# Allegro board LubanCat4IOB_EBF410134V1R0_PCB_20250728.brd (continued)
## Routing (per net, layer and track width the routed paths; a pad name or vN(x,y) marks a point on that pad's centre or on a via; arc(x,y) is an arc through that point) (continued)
VBUS_TYPEC: length 50.2
  TOP w0.203: J30.A9 26.63,96.58 26.87,96.82 J30.B4
  TOP w0.254: v1(29.46,98.55) 29.46,98.04 29.37,97.94 J30.B9 29.37,96.85 29.13,96.61 J30.A4 29.13,95.37 29.04,95.28 29.04,94.9 28.83,94.68 v1(28.83,94.11) ; J30.B4 26.87,98.48 v1(26.8,98.55) ; v1(21.01,82.26) 20.7,82.57 20.7,92.2 20.32,92.58 20.32,93.83 v1(19.68,94.46)
  BOTTOM w0.152: U39.2 26.03,69.47 C206.1
  BOTTOM w0.254: v1(19.68,94.46) 27.79,94.46
  BOTTOM w0.305: v1(21.01,82.26) 20.83,82.08 20.83,81.54 20.14,80.85 20.14,75.56 20.45,75.25 25.58,75.25 27.49,73.34 27.49,69.95 27,69.46 C206.1
  vias: v1(26.8,99.54)
VCC3V3_SYS: length 12.1
  BOTTOM w0.305: C17.1 8.81,46.36 9.45,47.01 9.45,52.2 8.69,52.97 C10.1 R6.1
  vias: v1(6.99,45.08) v1(6.99,44.07) v1(8,45.08) v1(8,44.07) v1(19.3,42.67) v1(19.3,41.53) v1(123.06,63.75) v1(124.08,63.75) v1(126.87,95.12) v1(126.87,94.11)
VCC5V0_SYS: length 56.8
  TOP w0.152: J3.1 J3.2 ; J3.4 v1(24.11,27.08) J3.3 ; J3.5 J3.6
  TOP w0.254: U4.5 v1(2.08,70.61)
  TOP w0.305: v1(18.54,19.81) 17.4,19.81 16.26,18.67 16.26,14.35 15.38,13.47 R36.1 R35.1 R34.1
  BOTTOM w0.152: v1(24.11,27.08) 24.49,26.7 24.49,22.94 24.94,22.48 R238.1 ; 128.52,89.93 v1(128.52,89.86) 128.52,89.66 128.61,89.58 C136.1 ; C31.1 v1(19.43,27.68) ; U39.12 22.99,71.89 C205.1
  BOTTOM w0.381: v1(21.46,73.4) C204.1 22.44,72.44 C205.1 ; R18.1 8,65.28 7.75,65.02 7.75,62.77 6.99,62.01 5,62.01 ; C29.1 3.93,62.48 3.55,62.86 2.46,62.86 2.08,63.24 v1(2.08,70.61)
  BOTTOM w0.508: R11.1 9.53,58.7 8.51,57.69 v1(6.44,57.69)
  vias: v1(4.45,59.69) v1(4.45,58.69) v1(4.45,57.69) v1(5.44,59.69) v1(5.44,58.69) v1(5.44,57.69) v1(6.44,59.69) v1(6.44,58.69) v1(19.43,30.68) v1(19.43,29.68) v1(19.43,28.68) v1(19.68,92.84) v1(20.43,30.68) v1(20.43,29.68) v1(20.43,28.68) v1(20.43,27.68) v1(20.57,48.89) v1(20.94,92.84) v1(21.46,48.89) v1(22.48,82.29) v1(23.37,82.29) v1(89.03,101.09) v1(90.04,101.09) v1(102.36,101.09) v1(103.38,101.09) v1(123.06,58.67) v1(124.08,58.67) v1(126.62,64.64) v1(126.62,63.63) v1(126.62,42.54) v1(126.62,41.53) v1(127.64,64.64) v1(127.64,63.63) v1(127.64,42.54) v1(127.64,41.53) v1(128.52,90.66)
VCC_1V8_S0: length 59.4
  TOP w0.203: 28.5,29.72 27.71,28.93 J3.21 J3.22
  TOP w0.508: v1(56.01,68.2) v1(56.01,67.05) 55.02,66.06 52.2,66.06 45.72,59.59 45.72,53.97 31.88,40.13 31.88,30.22 31.37,29.72 28.5,29.72
  BOTTOM w0.381: R185.1 v1(56.01,67.05) ; R188.1 v1(56.01,68.2)
VCC_1V8_S3: length 206.1
  TOP w0.203: J3.19 J3.20 27.31,23.49 v1(27.3,23.48)
  TOP w0.305: v1(25.79,23.5) 24.71,22.43 v1(17.4,22.43) 9.58,22.43 8.76,23.24 8.76,29.38 8.15,29.99 3.68,29.99 v1(3.56,29.86)
  TOP w0.381: v1(17.91,8.91) 99.97,8.91 101.73,10.67 101.73,26.93 102.11,27.31 R61.1
  ART03 w0.381: v1(3.56,29.86) 2.73,30.69 2.73,40.45 1.4,41.78 1.4,79.5 v1(1.78,79.88)
  BOTTOM w0.254: v1(1.78,79.88) 2.67,80.77 2.67,81.41 2.93,81.67 R46.1 R47.1
  BOTTOM w0.381: v1(17.4,22.43) 17.91,21.92 v1(17.91,8.91)
  BOTTOM w0.508: v1(25.79,23.5) C35.1 27.28,23.5 v1(27.3,23.48)
VCC_3V3_S3: length 251.8
  TOP w0.203: J3.14 J3.13 26.11,29.26 25.57,29.8 v1(25.57,31.74)
  TOP w0.305: v1(27.3,19.81) v1(21.73,19.81)
  TOP w0.381: v1(19.68,45.97) 18.31,45.97 17.55,46.73 17.55,65.78 16.88,66.46 16.88,76.49 16.11,77.26 v1(9.78,77.26)
  TOP w0.508: R56.1 109.98,29.46 109.7,29.74 104.5,29.74 104.04,30.2 104.04,31.64 103.65,32.03 101.35,32.03 100.61,31.29 100.61,11.07 99.82,10.29 v1(18.54,10.29)
  ART03 w0.381: v1(44.83,78.21) 31.24,78.21 30.48,77.45 30.48,70.76 29.59,69.87 26.59,69.87 24.97,68.25 24.97,65.19 v1(24.26,64.48) v1(23.05,64.48) 23.04,64.46 v1(21.57,64.46)
  BOTTOM w0.152: v1(25.57,31.74) 25.54,31.77 C36.1
  BOTTOM w0.254: 27.31,19.8 v1(27.3,19.81) ; 24.89,65.79 24.89,66.8 23.99,67.7 U39.4 24.45,68.72 U39.3 ; 24.89,65.79 C211.1 ; 24.89,65.79 R232.1 v1(24.26,64.48) ; v1(23.05,64.48) 23.11,64.54 R230.1 ; U5.5 20.34,17.67 20.18,17.52 R25.1 ; v1(21.57,64.46) 21.59,64.46 21.97,64.85 R231.1 ; U6.5 25.18,17.67 R29.1
  BOTTOM w0.305: v1(21.73,19.81) C40.1 21.73,18.55 21.33,18.15 U5.5 ; 27.31,19.8 C42.1 27.31,18.55 26.91,18.15 U6.5
  BOTTOM w0.381: v1(9.78,77.26) 9.78,83.37 10.54,84.14 D5.2 ; v1(44.83,78.21) 45.33,78.71 R233.1
  BOTTOM w0.508: v1(19.68,45.97) 19.68,56.26 21.72,58.29 23.11,58.29 24.13,59.31 24.13,62.99 25.53,64.39 C211.1
  vias: v1(20.57,45.97) v1(21.46,34.03) v1(21.46,33.15) v1(24.77,31.74)
VCC_3V3_SD: length 5.3
  TOP w0.508: R56.2 109.97,27.3 C58.1 C59.1 110,24.74 J10.4
VCC_12V: length 10.8
  TOP w0.254: U4.1 5.2,72.97
  BOTTOM w0.254: v1(6.86,55.24) 6.1,56 R8.1
  BOTTOM w0.279: R15.1 v1(6.99,74.93)
  BOTTOM w0.508: v1(8.86,55.24) 10.79,55.24 11.3,55.75 R10.1
  vias: v1(6.99,76.96) v1(6.99,75.94) v1(7.87,76.96) v1(7.87,75.94) v1(7.87,74.93) v1(12.83,82.29) v1(12.83,81.28) v1(13.84,82.29) v1(13.84,81.28) v1(79.25,86.64) v1(80.14,86.64)
VCCA1V8_CODEC: length 40
  TOP w0.381: v1(57.79,60.32) v1(55.12,60.32)
  BOTTOM w0.254: R200.1 48.39,74.8 48.78,75.19 R207.1 C187.1
  BOTTOM w0.381: C187.1 52.83,73.78 53.59,73.02 53.59,70.74 54.99,69.34 57.03,69.34 57.79,68.58 v1(57.79,60.32) C165.1 57.49,59.13 C164.1 57.67,57.99 R184.2 ; v1(55.12,60.32) 54.24,61.2 C174.1 C175.1 54.24,64 52.58,65.66 52.58,68.83 52.32,69.09
VCCA3V3_CODEC: length 45.2
  TOP w0.305: v1(41.53,66.93) 42.16,67.56 44.02,67.56 45.34,68.88 45.9,68.88 46.46,69.44 46.46,78.38 44.45,80.39 R205.1 47.19,82.94 47.5,83.24 47.5,84.94 47.8,85.24 54.56,85.24 54.86,84.94 R192.2
  TOP w0.508: v1(42.29,62.48) 41.53,63.24 v1(41.53,65.44) v1(41.53,66.93)
  BOTTOM w0.381: R186.1 42.03,68.7 41.53,68.2 v1(41.53,66.93) ; v1(41.53,65.44) 42.06,65.44 R187.1
  BOTTOM w0.508: R189.2 40.72,61.71 C172.1 41.32,61.71 C173.1 v1(42.29,62.48)
VCCA_1V8_S0: length 147.3
  TOP w0.203: v1(27.56,29.73) 26.91,29.08 J3.17 J3.18
  TOP w0.254: v1(8.26,32.89) v1(8.26,37.97)
  TOP w0.305: v1(18.14,32.38) 12.67,32.38 12.17,32.89 v1(8.26,32.89)
  TOP w0.381: v1(25.43,50.04) 25.43,35.5 26.19,34.74 v1(27.57,34.74)
  ART03 w0.381: v1(34.16,69.34) 34.03,69.21 26.77,69.21 25.53,67.97 v1(25.53,62.85)
  ART03 w0.762: v1(58.67,35.43) 56.97,33.73 30.18,33.73 28.19,31.74 v1(27.57,31.74)
  BOTTOM w0.203: v1(8.26,32.89) 7.63,32.27 R30.2 ; R32.2 7.89,37.61 v1(8.26,37.97)
  BOTTOM w0.305: v1(27.57,31.74) 28.22,32.39 28.22,34.09 v1(27.57,34.74) 27.33,34.97 18.75,34.97 18.14,34.37 v1(18.14,32.38)
  BOTTOM w0.381: v1(58.67,35.43) 58.67,36.7 59.86,37.89 59.86,41.61 57.38,44.09 57.38,52.42 58.67,53.71 C162.1 C163.1 R184.1 ; v1(34.16,69.34) 34.16,69.34 33.78,69.34 33.15,69.98 33.15,73.17 33.66,73.67 R23.1 ; v1(25.43,50.04) 25.43,58.39 24.89,58.93 24.89,62.21 v1(25.53,62.85)
  BOTTOM w0.508: v1(27.57,31.74) C34.1 27.57,29.73 v1(27.56,29.73)
VCCA_3V3_S0: length 53.5
  TOP w0.203: J3.16 J3.15 26.51,29.68 v1(26.56,29.73)
  TOP w0.508: v1(26.57,31.74) 26.57,32.64 26.06,33.15 24.17,33.15 23.15,34.16 23.15,52.96 23.79,53.59 v1(29.08,53.59)
  BOTTOM w0.508: v1(29.08,53.59) 29.08,59.57 30.23,60.71 C170.1 C171.1 R189.1 ; v1(26.56,29.73) 26.53,29.75 C33.1 26.53,31.71 v1(26.57,31.74)
VDD_3V3: length 235.5
  TOP w0.254: v1(103.25,19.43) 105.05,17.63 120.75,17.63 121.8,18.68 R164.1 ; R164.1 R162.1 v1(124.97,18) ; R164.1 v1(123.83,18)
  ART03 w0.381: v1(78.74,92.96) 76.96,91.18 v1(74.04,91.18) 73.53,90.68 67.82,90.68 v1(67.18,90.04)
  BOTTOM w0.152: R150.1 R154.1 121.98,71.57 121.98,76.02 120.9,77.1 120.9,80.74 121.16,80.99 v1(121.16,81.68)
  BOTTOM w0.254: v1(122.56,81.52) 123.06,81.02 123.06,80.01 122.56,79.51 R148.1 R152.1 ; R130.1 67.94,90.8 v1(67.18,90.04) 67.18,90.03 R129.1 R127.1 64.25,89.88 Q7.1 ; R162.1 v1(124.97,18) ; R132.1 64.89,100.2 66.79,100.2 R135.1 R133.1 70.24,100.2 71.88,100.2 72.26,99.82 72.26,97.92 72.64,97.53 76.71,97.53 78.36,95.88 78.36,93.34 v1(78.74,92.96) ; R164.1 v1(123.83,18)
  BOTTOM w0.381: 12.57,13.08 12.19,13.46 9.91,13.46 9.53,13.08 R44.1 ; 12.57,13.08 12.85,13.36 16.07,13.36 17.2,14.48 17.2,21.67 16.51,22.35 v1(16.51,44.07) ; 12.57,13.08 R43.1 ; U9.16 45.59,48.01 46.11,47.49 C54.1 47.63,47.49 48.23,46.89 v1(48.23,42.42) ; Q6.2 95.77,44.42 C94.1 R110.1 95.77,41.78 96.15,41.4 98.81,41.4 99.19,41.02 99.19,19.81 99.57,19.43 v1(103.25,19.43) ; v1(74.04,91.18) 75.31,91.18 75.69,90.8 75.69,85.22 v1(75.31,84.83) ; v1(121.16,81.68) v1(121.16,82.68)
  BOTTOM w0.508: R240.2 C90.1 117.72,77.8 117.14,78.38 115.98,78.38 115.49,78.87 115.49,81.14 117.03,82.68 v1(121.16,82.68)
  BOTTOM w0.762: 59.56,45.32 59.56,51.18 61.09,52.7 61.09,55.32 61.85,56.08 61.85,71.19 61.44,71.59 61.44,75.02 64.95,78.53 66.14,78.53 67.14,79.53 68.85,79.53 74.16,84.83 v1(74.31,84.83) v1(75.31,84.83)
  vias: v1(29.1,44.32) v1(29.97,44.32) v1(30.99,44.32) v1(60.43,43.69) v1(61.44,43.69) v1(61.47,42.67) v1(91.69,85.34)
VDD_5V: length 72.4
  BOTTOM w0.254: Q9.1 64.71,96.22 65.4,96.91 69.72,96.91 70.1,96.53 70.1,94.87 70.38,94.59 71.6,94.59 73.03,96.01 74.93,96.01 75.56,95.38 75.56,91.95 76.3,91.21 76.3,87.07 D28.2
  BOTTOM w0.508: v1(60.45,48.3) 60.45,50.8 61.98,52.32 61.98,54.84 62.71,55.57 62.71,71.57 62.31,71.97 62.31,74.49 63.4,75.58 65.63,75.58 66.19,76.14 66.19,77.26 67.56,78.63 69.08,78.63 74.14,83.69 76.27,83.69 77.14,84.56 D28.2
  vias: v1(29.12,49.15) v1(29.97,49.15) v1(61.47,48.3)
5V0_CAM0/1:
  vias: v1(128.27,55.88) v1(128.27,54.86) v1(129.29,55.88) v1(129.29,54.86)
5V0_CAM2/3:
  vias: v1(128.27,33.88) v1(128.27,32.86) v1(129.29,33.88) v1(129.29,32.86)
B_DM1: length 28.9
  TOP w0.135: J16.2 87.05,93.38 86.92,93.52 86.92,94.76 87.23,95.06 90.68,95.06 93.4,92.34 96.1,92.34 96.37,92.07 96.37,90.17 v1(96.11,89.91)
  BOTTOM w0.135: R116.1 89.71,82.97 89.71,83.49 89.49,83.7 89.49,84.02 89.4,84.12 U16.7 U16.4 89.4,86.06 89.49,86.16 89.49,86.74 90.26,87.5 95.5,87.5 96.33,88.33 96.33,89.69 v1(96.11,89.91)
B_DM2: length 10.3
  TOP w0.135: v1(86.96,86.82) 86.97,86.82 87.31,87.17 87.75,87.17 88,87.41 88,89.13 87.66,89.47 87.66,89.92 J16.11
  BOTTOM w0.135: v1(86.96,86.82) 87.14,87.01 87.15,87.01 87.28,87.14 87.84,87.14 88.09,86.89 88.09,86.25 87.9,86.06 U16.1 U16.10 87.9,84.21 88.09,84.02 88.09,83.38 R112.1
B_DM3: length 36.5
  BOTTOM w0.135: J17.2 102,89.89 101.87,89.75 99.35,89.75 96.27,86.67 96.27,79.01 98.81,76.47 98.81,69.1 99.28,68.62 99.28,64.4 98.58,63.7 98.06,63.7 97.87,63.89 U18.9 U18.2 96.02,63.89 95.83,63.7 95.17,63.7 R114.1
B_DP1: length 29.6
  TOP w0.135: v1(96.77,89.91) 96.68,90.01 96.68,92.2 96.23,92.65 93.53,92.65 90.81,95.38 87.1,95.38 86.61,94.89 86.61,93.52 86.47,93.38 J16.3
  BOTTOM w0.135: R117.1 90.04,83.05 90.04,83.59 89.81,83.83 89.81,84.02 89.9,84.12 U16.6 U16.5 89.9,86.06 89.81,86.16 89.81,86.61 90.39,87.19 95.63,87.19 96.65,88.2 96.65,89.79 v1(96.77,89.91)
B_DP2: length 10.4
  TOP w0.135: v1(86.96,87.48) 87.55,87.48 87.69,87.62 87.69,89 86.5,90.18 J16.12
  BOTTOM w0.135: R113.1 88.4,82.68 U16.9 U16.2 88.4,87.02 87.97,87.45 86.99,87.45 v1(86.96,87.48)
B_DP3: length 36.2
  BOTTOM w0.135: J17.3 102,89.31 101.87,89.44 99.48,89.44 96.58,86.54 96.58,79.14 99.12,76.6 99.12,69.23 99.59,68.75 99.59,64.27 98.71,63.39 U18.10 U18.1 95.96,63.39 95.96,63.38 95,63.38 R115.1
BAT_RTC: length 6.4
  BOTTOM w0.381: J8.1 16.07,84.59 D6.2 C50.1 12.44,84.59 11.39,85.64 D5.1
BD_CH3: length 5.2
  TOP w0.152: v1(32.77,76.96) 32.91,76.81 J4.48
  BOTTOM w0.152: R23.2 33.66,75.44 R24.1 C38.1 33.27,77.47 v1(32.77,76.96)
CAM0/1_PWR_EN: length 110.3
  TOP w0.152: J5.69 62.88,29.19 62.31,29.77 62.31,32.18 61.99,32.49 v1(60.1,32.49)
  ART03 w0.14: v1(126.11,59.56) 126.11,58.64 126.33,58.42 128.37,58.42 128.78,58.01 128.78,55.55 128.93,55.4 129.44,55.4 129.77,55.07 129.77,43.53 128.27,42.04 122.29,42.04 121.66,41.4 119.13,41.4 115.06,45.46 102.87,45.46 102.36,44.96 102.36,34.97 102.06,34.67 62.28,34.67 v1(60.1,32.49)
  BOTTOM w0.152: v1(126.11,59.56) 126.11,59.57 R165.1
CAM0_NRST: length 174.9
  TOP w0.152: v1(18.82,69.21) 18.31,69.72 18.31,72.59 18.62,72.9 23.44,72.9 24.51,73.96 J4.6
  ART03 w0.14: v1(119.63,42.67) 115.66,46.64 115.61,46.64 115.58,46.67 101.23,46.67 100.46,45.9 100.46,40.54 100.05,40.13 59.13,40.13 58.57,40.69 54.79,40.69 54.28,40.18 14.91,40.18 14.63,40.46 14.63,65.56 18.29,69.21 v1(18.82,69.21)
  BOTTOM w0.152: J21.22 125.72,54.75 124.76,55.7 122.25,55.7 118.51,51.96 118.51,43.79 v1(119.63,42.67)
CAM0_PWDN: length 178.6
  TOP w0.152: J4.4 24.11,74.34 23.81,74.04 18.52,74.04 17.83,73.35 17.83,70.22 v1(17.82,70.21)
  ART03 w0.14: v1(128.91,45.85) 128.91,43.68 128.28,43.06 124.34,43.06 123.83,42.54 121.93,42.54 121.16,41.78 119.25,41.78 115.19,45.85 102.23,45.85 101.73,45.34 101.73,39.17 101.42,38.86 58.88,38.86 58.5,38.48 55.93,38.48 55.55,38.86 14.22,38.86 13.74,39.34 13.74,66.27 17.69,70.21 v1(17.82,70.21)
  BOTTOM w0.152: v1(128.91,45.85) 129.54,46.48 129.54,51 129.29,51.25 J21.15
CAM1_NRST: length 162.4
  TOP w0.152: v1(124.97,44.96) 125.26,45.25 J22.22 ; v1(24,75.99) 25.48,75.99 25.71,75.76 J4.12
  ART03 w0.14: v1(24,75.99) 24,74.52 20.24,70.76 20.24,69.04 19.91,68.71 18.49,68.71 15.14,65.35 15.14,41.02 15.39,40.77 53.92,40.77 54.33,41.17 58.85,41.17 59.26,40.77 99.42,40.77 99.82,41.17 99.82,46.48 100.46,47.12 115.82,47.12 119.76,43.18 123.79,43.18 124.97,44.35 v1(124.97,44.96)
CAM1_PWDN: length 170.7
  TOP w0.152: v1(120.78,42.67) 119.48,43.97 119.48,48.36 119.87,48.75 J22.15 ; v1(18.82,70.21) 18.82,72.03 19.18,72.39 23.62,72.39 24.91,73.68 J4.8
  ART03 w0.14: v1(120.78,42.67) 120.29,42.19 119.43,42.19 115.4,46.23 101.6,46.23 101.09,45.72 101.09,39.71 100.95,39.57 14.33,39.57 14.19,39.71 14.19,65.99 17.85,69.66 18.27,69.66 v1(18.82,70.21)
CAM2/3_PWR_EN: length 73.5
  TOP w0.152: J5.71 63.28,29.68 62.87,30.1 62.87,30.97 v1(63.35,31.45)
  ART03 w0.14: v1(63.35,31.45) 65.04,33.15 103.63,33.15 104.14,32.64 104.14,30.86 104.5,30.5 113.94,30.5 121.93,38.49 v1(123.57,38.49)
  BOTTOM w0.152: R167.1 v1(123.57,38.49)
CAM2_NRST: length 210.9
  TOP w0.152: v1(22,76.99) 25.75,76.99 26.51,76.23 J4.16
  ART03 w0.14: v1(130.18,28.57) 129.67,28.07 129.67,21.59 127.76,19.68 123.95,19.68 123.32,19.05 123.32,17.78 123.06,17.52 107.44,17.52 105.28,15.37 81.41,15.37 81.15,15.11 75.06,15.11 74.58,15.59 66.75,15.59 66.08,14.92 63.31,14.92 62.65,15.59 33.69,15.59 31.18,18.09 10.99,18.09 9.14,19.94 9.14,24.38 8.76,24.76 8.76,29.97 11.37,32.57 11.37,66.08 17.14,71.86 18.64,71.86 22.53,75.74 22.53,76.46 v1(22,76.99)
  BOTTOM w0.203: J23.22 127.4,32.75 128.14,32 129.67,32 129.9,31.77 129.9,28.85 v1(130.18,28.57)
CAM2_PWDN: length 207.3
  TOP w0.152: J4.14 26.11,75.99 25.63,76.48 22.49,76.48 v1(22,75.99)
  ART03 w0.14: v1(22,75.99) 18.38,72.36 16.94,72.36 10.79,66.22 10.79,32.89 8.26,30.35 8.26,24.51 8.64,24.13 8.64,19.54 10.93,17.25 31.29,17.25 33.55,14.98 62.36,14.98 62.91,14.43 66.37,14.43 66.92,14.98 74.3,14.98 74.83,14.45 82.91,14.45 83.19,14.73 105.54,14.73 107.44,16.64 116.08,16.64 116.46,17.02 123.95,17.02 124.23,17.3 124.23,18.82 124.59,19.18 128.14,19.18 130.18,21.21 v1(130.18,25.53)
  BOTTOM w0.152: v1(130.18,25.53) 129.03,26.67 129.03,28.83 128.75,29.11 127.44,29.11 127.29,29.25 J23.15
CAM3_NRST: length 192.5
  TOP w0.152: v1(24,77.99) 27.17,77.99 27.71,77.44 J4.22
  TOP w0.203: v1(113.67,18.16) 114.3,18.79 120.4,18.79 123.7,22.1 123.7,22.99 123.96,23.25 J24.22
  ART03 w0.14: v1(24,77.99) 23.45,77.44 23.45,74.63 19.66,70.84 17.65,70.84 12.7,65.89 12.7,37.71 12.26,37.27 12.26,31.69 9.78,29.21 9.78,25.27 10.16,24.89 10.16,21.08 11.76,19.48 13.89,19.48 14.2,19.18 31.5,19.18 34.04,16.64 76.83,16.64 77.09,16.38 104.95,16.38 107.24,18.67 113.16,18.67 v1(113.67,18.16)
CAM3_PWDN: length 196.2
  TOP w0.152: v1(112.65,18.16) 113.79,19.3 120.14,19.3 123.06,22.22 123.06,25.53 124.29,26.75 J24.15 ; J4.20 27.31,77.08 26.97,77.42 23.57,77.42 v1(23,77.99)
  ART03 w0.14: v1(112.65,18.16) 107.44,18.16 105.16,15.87 81.15,15.87 80.9,15.62 75.44,15.62 74.93,16.13 33.91,16.13 31.39,18.64 11.71,18.64 9.65,20.7 9.65,24.64 9.27,25.02 9.27,29.59 11.81,32.13 11.81,37.45 12.26,37.9 12.26,66.2 17.4,71.35 18.75,71.35 18.81,71.41 18.83,71.41 22.97,75.56 22.97,75.58 23.01,75.61 23.01,77.98 v1(23,77.99)
CAN1_H: length 25.5
  BOTTOM w0.305: U12.7 72.39,41.31 R78.1 72.77,40.6 72.77,35.29 D24.2 72.77,31.73 72.77,28.7 71.12,27.05 71.12,21.97 70.61,21.46 R74.1
CAN1_L: length 25.5
  BOTTOM w0.305: R75.1 72.01,21.46 71.58,21.89 71.58,26.79 73.28,28.49 73.28,31.73 D25.2 73.28,35.29 73.28,40.6 R78.2 73.66,41.31 U12.6
CAN1_RX_M1: length 99.4
  TOP w0.152: J4.30 29.31,74.31 28.74,73.74 27.84,73.74 26.7,72.59 v1(25.84,72.59)
  ART03 w0.14: v1(69.09,48.89) 69.09,47.42 68.86,47.19 64.21,47.19 62.92,45.9 24.21,45.9 22,48.11 16.54,48.11 16.1,48.54 16.1,64.97 18.82,67.69 21.39,67.69 22.25,68.55 22.25,70.71 23.65,72.11 25.36,72.11 v1(25.84,72.59)
  BOTTOM w0.152: v1(69.09,48.89) 69.09,49.4 69.6,49.91 74.68,49.91 74.93,49.66 U12.4
CAN1_TX_M1: length 95.7
  TOP w0.152: J4.28 28.91,74.48 28.61,74.18 27.49,74.18 26.49,73.18 25.74,73.18 25.16,72.59 v1(24.84,72.59)
  ART03 w0.14: v1(69.98,48.89) 69.98,46.43 69.62,46.07 65.35,46.07 64.74,45.46 23.88,45.46 21.72,47.62 16.26,47.62 15.62,48.26 15.62,65.2 18.62,68.2 20.04,68.2 20.57,68.73 21.23,68.73 21.69,69.19 21.69,71.47 22.8,72.58 24.83,72.58 v1(24.84,72.59)
  BOTTOM w0.152: v1(69.98,48.89) 70.99,48.89 71.12,48.77 U12.1
CAN2_H: length 24.8
  BOTTOM w0.305: U13.7 64.26,41.31 R79.1 64.64,40.6 64.64,35.29 D26.2 64.64,31.73 64.64,21.84 64.26,21.46 R76.1
CAN2_L: length 24.9
  BOTTOM w0.305: U13.6 65.53,41.31 R79.2 65.22,40.67 65.22,35.22 D27.2 66.66,33.51 65.15,32 65.15,21.84 65.66,21.33 R77.1
CAN2_RX_M0: length 87
  TOP w0.152: J4.36 30.51,73.26 29.91,72.66 v1(29.08,72.66)
  ART03 w0.14: v1(67.82,48.89) 62.99,48.89 61.98,49.91 44.6,49.91 43.97,49.27 32.51,49.27 30.51,51.28 17.78,51.28 17.25,51.81 17.25,64.79 19.13,66.67 21.77,66.67 27.15,72.06 28.48,72.06 v1(29.08,72.66)
  BOTTOM w0.152: v1(67.82,48.89) 67.82,49.76 67.67,49.91 66.95,49.91 66.8,49.76 U13.4
CAN2_TX_M0: length 80.9
  TOP w0.152: J4.34 30.11,73.6 29.66,73.14 28.57,73.14 v1(28.08,72.66)
  ART03 w0.14: v1(61.47,49.4) 44.96,49.4 44.32,48.77 32.26,48.77 30.35,50.67 17.53,50.67 16.64,51.56 16.64,64.87 18.95,67.18 21.62,67.18 27.09,72.66 v1(28.08,72.66)
  BOTTOM w0.152: v1(61.47,49.4) 61.87,49.81 62.84,49.81 62.99,49.66 U13.1
CTP0_INT: length 87.7
  TOP w0.152: v1(123.9,82.7) 123.9,83.01 124.1,83.21 125.09,83.21 125.4,82.9 125.4,76.3 v1(125.35,76.24) ; J6.44 57.68,79.42 v1(58.65,80.39)
  ART03 w0.14: v1(58.65,80.39) 59.17,80.91 59.17,83.1 61.06,84.99 70.23,84.99 71.17,84.05 105.74,84.05 107.19,82.6 113.56,82.6 114.12,82.04 115.77,82.04 116.15,82.42 120.14,82.42 120.45,82.12 123.32,82.12 v1(123.9,82.7)
  BOTTOM w0.152: R147.2 124.21,76.45 124.41,76.24 v1(125.35,76.24) J19.11
CTP0_RST: length 142.3
  TOP w0.152: v1(61.47,19.43) 61.28,19.62 J5.62
  ART03 w0.14: v1(127.64,58.93) 128.14,59.43 131.11,59.43 131.32,59.23 131.32,57.73 131.11,57.53 130.25,57.53 130.05,57.33 130.05,56.64 130.71,55.98 130.71,55.85 130.8,55.76 130.8,37.96 130.18,37.34 130.18,30.1 128.78,28.7 128.78,22.61 126.86,20.7 106.17,20.7 103.89,18.41 78.74,18.41 77.72,19.43 v1(61.47,19.43)
  BOTTOM w0.152: v1(127.64,58.93) 127,58.29 125.73,58.29 125.09,58.93 125.09,68.02 125.53,68.45 125.53,72.85 124.71,73.66 123.95,73.66 123.56,74.05 R151.2 124.21,75.44 124.51,75.74 J19.12
CTP1_INT: length 86.1
  TOP w0.152: J20.11 124.6,71.74 v1(124.33,72.01) 123.44,72.9 123.44,74.17 122.81,74.8 122.81,75.82 122.3,76.33 120.9,76.33 120.4,76.83 120.4,80.87 120.24,81.02 119.76,81.02 v1(118.87,81.91) ; J6.46 58.08,78.94 59.15,80.01 59.15,80.91 v1(59.65,81.41)
  ART03 w0.14: v1(59.65,81.41) 59.65,82.89 61.26,84.5 69.98,84.5 70.92,83.56 105.26,83.56 107.27,81.56 116.15,81.56 116.51,81.91 v1(118.87,81.91)
  BOTTOM w0.152: R149.2 v1(124.33,72.01)
CTP1_RST: length 77.9
  TOP w0.152: v1(121.44,80.52) 120.9,79.98 120.9,77.09 121.16,76.83 122.55,76.83 123.35,76.04 123.35,75.11 123.9,74.57 123.9,73.46 v1(124.33,73.02) 125.11,72.25 J20.12 ; v1(65.28,80.41) 65.28,79.01 62.88,76.61 J6.70
  ART03 w0.14: v1(65.28,80.41) 65.8,80.92 67.28,80.92 68.68,79.53 89.51,79.53 90.12,80.14 96.41,80.14 97.54,79.01 117.49,79.01 118.41,79.93 120.85,79.93 v1(121.44,80.52)
  BOTTOM w0.152: R153.2 v1(124.33,73.02)
DBG_RX: length 4.3
  BOTTOM w0.152: U6.2 30.07,17.02 30.23,16.87 30.23,15.14 30.07,14.98 R27.2
DBG_RXD: length 4.9
  BOTTOM w0.152: R27.1 Z4.1 27.3,13.96 26.25,12.91 J7.3
DBG_TX: length 1.6
  BOTTOM w0.152: U5.4 21.33,15.99 20.71,15.37 R26.2
DBG_TXD: length 4.9
  BOTTOM w0.152: J7.2 23.75,12.57 22.74,13.58 Z3.1 R26.1
DEBUG_RX: length 49.5
  TOP w0.152: v1(25.78,16.37) 26.28,15.87 62.99,15.87 64.48,17.36 J5.78
  BOTTOM w0.152: U6.4 v1(25.78,16.37) 25.16,16.37 R29.2
DEBUG_TX: length 59.1
  TOP w0.152: v1(19.56,15.75) 19.94,15.37 63.37,15.37 64.88,16.87 J5.80
  BOTTOM w0.152: v1(19.56,15.75) R25.2 20.2,16.52 20.71,17.02 U5.2
EARPHONE_CTL: length 181.8
  TOP w0.152: J5.72 63.28,23.97 64.01,23.24 64.01,17.65 62.74,16.38 v1(31.11,16.38)
  ART03 w0.14: v1(31.11,16.38) 30.71,16.79 10.64,16.79 7.24,20.19 7.24,30.96 10.01,33.73 10.01,75.03 10.9,75.92 10.9,83.18 12.14,84.43 18.34,84.43 19.71,85.8 22.1,85.8 22.48,86.18 22.48,87.39 22.72,87.63 36.63,87.63 38.84,89.84 43.74,89.84 45.08,91.18 v1(47.75,91.18)
  BOTTOM w0.152: v1(47.75,91.18) 47.62,91.06 47.62,84 46.56,82.94 R216.1
EXT_PWR_EN: length 58.4
  TOP w0.152: v1(11.18,20.83) 11.66,20.34 12.34,20.34 12.8,20.8 28.96,20.8 29.31,21.16 J3.30
  ART03 w0.14: v1(19.18,37.72) 13.34,37.72 12.7,37.08 12.7,31.24 10.29,28.83 10.29,25.61 10.67,25.23 10.67,21.33 v1(11.18,20.83)
  BOTTOM w0.152: v1(19.18,37.72) 19.68,37.21 25.15,37.21 25.52,37.58 R3.1 ; R37.1 8.9,20.83 v1(11.18,20.83)
FAN: length 1.8
  BOTTOM w0.152: R10.2 R11.2
FAN_PWM: length 80.7
  TOP w0.152: J5.63 61.68,29.42 61.85,29.59 61.85,31.62 61.47,32 56.39,32 56.13,32.26 v1(56.13,35.43)
  ART03 w0.14: v1(13.18,59.77) 13.18,39.01 13.84,38.35 27.94,38.35 29.34,36.96 47.75,36.96 48.51,36.19 55.37,36.19 v1(56.13,35.43)
  BOTTOM w0.152: R13.1 12.96,59.99 v1(13.18,59.77)
FUSB302_INT: length 102.9
  TOP w0.152: J5.68 62.48,23.37 62.99,22.86 62.99,18.54 61.72,17.27 34.45,17.27 v1(33.43,18.29)
  BOTTOM w0.152: U39.5 23.49,66.92 R232.2 23.64,65.54 23.64,64.15 23.11,63.63 23.11,61.97 18.29,57.15 18.29,37.34 18.82,36.8 28.63,36.8 30.4,35.03 30.4,33.1 31.73,31.77 31.73,29.78 33.4,28.11 33.4,23.75 32.65,23 32.65,19.07 v1(33.43,18.29)
GMAC1_INT: length 71.7
  TOP w0.152: J6.48 58.48,78.58 59.65,79.75 v1(59.65,80.39)
  ART03 w0.14: v1(97.79,82.55) 97.18,83.16 70.59,83.16 69.75,84 61.52,84 60.15,82.63 60.15,80.89 v1(59.65,80.39)
  BOTTOM w0.152: v1(97.79,82.55) 97.79,79.63 100.58,76.83 100.58,62.23 101.09,61.72 R96.1
GMAC1_MCLK_INOUT: length 92.3
  TOP w0.132: v1(101.85,64.26) 101.22,63.63 95.5,63.63 93.45,65.68 73.42,65.68 67.79,60.05 63.74,60.05 61.13,57.44 55.34,57.44 36.91,39.02 J3.67
  BOTTOM w0.132: v1(101.85,64.26) 102.49,64.9 103.88,64.9 R98.1 R97.1
GMAC1_MDC: length 127.2
  TOP w0.132: J3.95 42.51,30.73 42.9,31.11 48.84,31.11 50.01,32.28 50.01,41.54 50.35,41.87 51.04,41.87 60.09,50.93 63.96,50.93 66.68,53.65 70.61,53.65 76.54,59.58 87.87,59.58 88.12,59.32 90.17,57.28 v1(90.17,56.39)
  BOTTOM w0.132: U14.13 116.32,69.32 R93.2 117.24,70.24 121.15,70.24 122.03,69.36 122.03,57.51 115.13,50.62 102.04,50.62 101.78,50.87 101.78,50.95 96.82,55.91 90.64,55.91 v1(90.17,56.39)
GMAC1_MDIO: length 123.3
  TOP w0.132: v1(91.19,56.39) 90.68,55.88 89.92,55.88 89.66,56.13 89.66,57.17 87.69,59.14 76.72,59.14 70.79,53.21 66.86,53.21 63.56,49.91 59.69,49.91 51.41,41.63 51.41,30.66 50.57,29.82 43.28,29.82 42.91,29.45 J3.97
  BOTTOM w0.132: U14.14 115.87,68.92 116.09,68.71 R94.2 117.24,68.19 119.97,68.19 121.59,66.57 121.59,57.71 114.94,51.05 102.3,51.05 96.97,56.39 v1(91.19,56.39)
GMAC1_RSTN: length 88.9
  TOP w0.152: v1(60.65,81.41) 60.2,80.95 60.2,79.37 58.88,78.06 J6.50
  ART03 w0.14: v1(60.65,81.41) 61.14,81.89 61.14,82.83 61.82,83.51 69.42,83.51 70.31,82.63 96.82,82.63 97.47,81.98 98.37,81.98 99.07,82.67 105.5,82.67 107.07,81.1 116.56,81.1 116.9,81.44 119.41,81.44 v1(119.89,81.91)
  BOTTOM w0.152: U14.12 115.56,69.72 C78.1 R105.2 121.04,70.87 121.44,71.27 121.44,75.61 120.43,76.62 120.43,81.37 v1(119.89,81.91)
GMAC1_RXCLK: length 104.3
  TOP w0.132: J3.85 40.51,34.52 40.97,34.97 44.83,34.97 45.34,35.48 45.34,41.57 56.88,53.11 63.05,53.11 65.84,55.9 69.51,55.9 75.4,61.78 90.92,61.78 91.19,61.52 v1(91.19,60.32)
  BOTTOM w0.132: R89.1 R83.1 110.35,59.92 110.35,58.25 109.89,57.79 106.01,57.79 103.06,60.75 96.89,60.75 96.75,60.61 96.75,60.12 96.62,59.98 96.36,59.98 96.23,60.12 96.23,60.61 96.09,60.75 95.83,60.75 95.7,60.61 95.7,60.12 95.56,59.98 95.3,59.98 95.17,60.12 95.17,60.61 95.04,60.75 94.77,60.75 94.64,60.61 94.64,60.12 94.51,59.98 94.24,59.98 94.11,60.12 94.11,60.61 93.98,60.75 93.72,60.75 93.58,60.61 93.58,60.12 93.45,59.98 93.19,59.98 93.06,60.12 93.06,60.61 92.92,60.75 92.66,60.75 92.53,60.61 92.53,60.12 92.4,59.98 92.13,59.98 92,60.12 92,60.61 91.87,60.75 91.61,60.75 v1(91.19,60.32)
GMAC1_RXD0: length 104.3
  TOP w0.132: J3.87 40.91,34.09 41.36,34.53 45.75,34.53 46.39,35.18 46.39,42 57.06,52.67 63.23,52.67 66.02,55.46 69.73,55.46 75.61,61.35 89.91,61.35 90.17,61.08 v1(90.17,60.32)
  BOTTOM w0.132: R84.1 R80.2 112.59,59.87 112.59,58.53 112.85,58.27 112.85,57.89 112.66,57.7 112.48,57.7 112.19,57.99 112,57.99 111.82,57.81 111.82,57.62 112.1,57.33 112.1,57.14 111.42,56.46 105.32,56.46 103.23,58.55 102.77,58.55 102.63,58.68 102.63,59.02 102.5,59.16 102.24,59.16 102.11,59.02 102.11,58.68 101.97,58.55 101.71,58.55 101.58,58.68 101.58,59.02 101.44,59.16 101.18,59.16 101.05,59.02 101.05,58.68 100.92,58.55 91.03,58.55 90.64,58.93 90.64,59.34 90.17,59.82 v1(90.17,60.32)
GMAC1_RXD1: length 104
  TOP w0.132: v1(90.17,59.05) 89.66,59.56 89.66,60.64 89.4,60.91 75.79,60.91 69.91,55.03 66.2,55.03 63.41,52.24 57.24,52.24 47.68,42.67 47.68,34.87 46.9,34.1 41.73,34.1 41.31,33.68 J3.89
  BOTTOM w0.132: v1(90.17,59.05) 90.17,58.69 90.75,58.11 103.05,58.11 105.14,56.02 112.32,56.02 112.62,56.33 112.62,56.51 112.45,56.69 112.45,56.87 112.64,57.06 112.82,57.06 113,56.89 113.18,56.89 113.37,57.07 113.37,57.26 113.2,57.43 113.2,57.62 113.38,57.81 113.57,57.81 113.74,57.63 113.93,57.63 114.11,57.82 114.11,58.19 113.74,58.56 113.74,59.88 R81.2 R85.1
GMAC1_RXD2: length 102.4
  TOP w0.132: v1(89.15,60.32) 89.03,60.45 76.08,60.45 70.22,54.59 66.38,54.59 63.59,51.8 58.07,51.8 49.02,42.75 49.02,40.1 48.16,39.24 48.16,34.31 47.5,33.66 42.1,33.66 41.71,33.27 J3.91
  BOTTOM w0.132: v1(89.15,60.32) 89.66,59.82 89.66,58.55 90.55,57.66 102.89,57.66 104.96,55.58 112.5,55.58 114.99,58.07 114.99,58.39 114.87,58.5 114.87,59.87 R91.1 R87.1
GMAC1_RXD3: length 102.1
  TOP w0.132: J3.93 42.11,31.99 42.38,32.26 47.52,32.26 49.45,34.19 49.45,41.81 50.29,42.65 50.7,42.65 52.55,44.5 52.55,45.31 58.6,51.36 63.78,51.36 66.56,54.15 70.4,54.15 76.26,60.01 88.19,60.01 v1(89.15,59.05)
  BOTTOM w0.132: v1(89.15,59.05) 89.15,58.44 90.37,57.22 102.67,57.22 104.74,55.15 112.68,55.15 116.01,58.48 116.01,59.87 R82.2 R88.1
GMAC1_RXDV_CRS: length 104.3
  TOP w0.132: J3.83 40.11,35.17 40.38,35.43 44.58,35.43 44.9,35.76 44.9,41.75 56.7,53.55 62.87,53.55 65.66,56.34 69.33,56.34 75.22,62.22 91.43,62.22 91.69,61.95 91.69,59.56 v1(92.2,59.05)
  BOTTOM w0.132: v1(92.2,59.05) 97.18,59.05 97.89,59.77 98.6,59.77 98.73,59.63 98.73,59.44 98.86,59.31 99.13,59.31 99.26,59.44 99.26,59.63 99.39,59.77 99.65,59.77 99.79,59.63 99.79,59.44 99.92,59.31 100.18,59.31 100.31,59.44 100.31,59.63 100.45,59.77 102.77,59.77 105.64,56.89 110.29,56.89 110.54,57.15 110.72,57.15 110.94,56.93 111.15,56.93 111.33,57.1 111.33,57.29 111.1,57.52 111.1,57.71 111.44,58.05 111.44,59.87 R92.1 R90.1
GMAC1_TXCLK: length 128.2
  TOP w0.132: J3.69 37.31,38.8 55.52,57.01 61.31,57.01 63.92,59.62 67.97,59.62 73.6,65.25 93.14,65.25 95.39,62.99 101.73,62.99 102.17,62.55 102.17,57.34 102.74,56.77 102.74,55.83 v1(103.48,55.09)
  BOTTOM w0.132: v1(103.48,55.09) 104.41,54.17 113.61,54.17 113.81,54.37 113.81,54.55 113.67,54.69 113.67,54.87 113.86,55.06 114.05,55.06 114.18,54.93 114.37,54.93 114.56,55.11 114.56,55.3 114.42,55.43 114.42,55.62 114.61,55.81 114.79,55.81 114.93,55.67 115.12,55.67 115.3,55.86 115.3,56.05 115.17,56.18 115.17,56.37 115.35,56.56 115.54,56.56 115.68,56.42 115.86,56.42 116.05,56.61 116.05,56.79 115.91,56.93 115.91,57.12 116.1,57.3 116.29,57.3 116.42,57.17 116.61,57.17 116.8,57.35 116.8,57.54 116.66,57.68 116.66,57.86 116.85,58.05 117.04,58.05 117.17,57.91 117.36,57.91 118.36,58.92 118.36,64.42 118.1,64.69 116.67,64.69 115.67,65.69 115.48,65.69 115,65.2 114.76,65.2 114.6,65.37 114.6,65.55 115.11,66.06 115.11,66.25 114.83,66.52 U14.20
GMAC1_TXD0: length 128.6
  TOP w0.132: v1(101.22,56.39) 101.22,61.59 100.7,62.12 95.03,62.12 92.78,64.37 73.96,64.37 68.33,58.74 64.36,58.74 61.75,56.13 55.88,56.13 38.11,38.37 J3.73
  BOTTOM w0.132: v1(101.22,56.39) 101.38,56.22 101.38,56.19 101.69,55.88 101.69,54.57 103.42,52.84 114.18,52.84 119.83,58.49 119.83,65.3 119.57,65.57 118.65,65.57 118.52,65.7 118.52,66.29 118.39,66.42 118.13,66.42 117.99,66.29 117.99,65.7 117.86,65.57 117.01,65.57 115.25,67.32 U14.18
GMAC1_TXD1: length 128.1
  TOP w0.132: v1(101.22,55.12) 100.75,55.59 100.75,61.18 100.24,61.68 95.21,61.68 94.85,61.68 92.6,63.94 74.14,63.94 68.51,58.31 64.64,58.31 61.96,55.62 55.99,55.62 38.51,38.15 J3.75
  BOTTOM w0.132: v1(101.22,55.12) 101.22,54.41 103.23,52.4 114.38,52.4 120.27,58.29 120.27,65.58 118.99,66.86 117.94,66.86 117.63,66.55 116.59,66.55 115.41,67.73 U14.17
GMAC1_TXD2: length 128.3
  TOP w0.132: J3.77 38.91,37.93 56.13,55.15 62.1,55.15 64.82,57.87 68.69,57.87 74.32,63.5 92.41,63.5 94.72,61.19 99.72,61.19 100.2,60.7 v1(100.2,56.39)
  BOTTOM w0.132: U14.16 115.59,68.13 116.41,67.3 119.16,67.3 120.71,65.76 120.71,58.09 114.57,51.96 103.01,51.96 100.71,54.26 100.71,55.88 v1(100.2,56.39)
GMAC1_TXD3: length 128.9
  TOP w0.132: J3.79 39.31,37.71 56.31,54.71 62.28,54.71 65,57.43 68.89,57.43 74.52,63.06 92.23,63.06 94.54,60.76 99.26,60.76 99.73,60.29 99.73,55.57 100.18,55.12 v1(100.2,55.12)
  BOTTOM w0.132: v1(100.2,55.12) 100.2,54.15 102.83,51.53 114.77,51.53 121.14,57.9 121.14,65.94 119.35,67.74 116.54,67.74 115.75,68.52 U14.15
GMAC1_TXEN: length 126.4
  TOP w0.132: v1(102.23,55.12) 101.73,55.62 101.73,61.97 101.15,62.55 95.21,62.55 92.96,64.81 73.78,64.81 68.15,59.18 64.1,59.18 61.49,56.57 55.7,56.57 37.71,38.58 J3.71
  BOTTOM w0.132: v1(102.23,55.12) 102.23,54.66 103.62,53.27 113.98,53.27 119.4,58.69 119.4,64.86 119.13,65.13 116.89,65.13 115.09,66.92 U14.19
HDMI0_TX_ON: length 15.4
  TOP w0.152: v1(67.02,72.57) 66.88,72.42 J6.89 ; v1(75.31,82.19) R145.1
  BOTTOM w0.152: v1(75.31,82.19) 75.31,82.12 73.77,80.58 73.77,79.79 73.53,79.55 72.61,79.55 69.46,76.4 69.46,75.01 v1(67.02,72.57)
HDMI_5V: length 16.6
  TOP w0.279: J18.18 v1(71,91.52)
  ART03 w0.381: v1(71,91.52) 67.39,91.52 v1(65.91,90.04)
  BOTTOM w0.254: R131.1 R128.1 v1(65.91,90.04)
  BOTTOM w0.508: D28.1 73.7,86.27 C124.1 73.4,88.31 D34.2 73.4,90.69 72.56,91.52 v1(71,91.52)
HDMI_EARC+: length 8.8
  TOP w0.107: J18.14 69,91.81 69.22,91.59 69.65,91.59 70.88,90.36 72.71,90.36 72.89,90.18 D32.2 72.89,89.67 73.38,89.18 73.38,88.23 C121.2
HDMI_EARC-: length 8.8
  TOP w0.107: J18.19 71.5,91.28 71.28,91.06 71,91.06 70.89,90.95 70.89,90.75 71,90.64 73.07,90.64 D29.2 73.66,89.53 73.66,89.03 R139.2 73.66,88.51 73.66,88 C122.2
HDMI_TX0_CEC_M0: length 62.7
  TOP w0.156: J4.60 35.31,77.67 33.81,79.17 33.81,80.63 30.75,83.69 v1(26.67,83.69)
  ART03 w0.14: v1(26.67,83.69) 37.16,83.69 38.45,84.98 39.82,84.98 40.34,85.5 42.77,85.5 45.95,88.67 56.16,88.67 v1(58.17,90.68)
  BOTTOM w0.152: R132.2 62.8,99.11 Q9.2 58.32,96.18 58.17,96.02 v1(58.17,90.68)
HDMI_TX0_D0N: length 23.8
  TOP w0.107: J6.37 56.48,72.2 56.42,72.26 56.42,72.55 56.8,72.93 56.8,73.85 v1(56.99,74.04)
  BOTTOM w0.107: v1(56.99,74.04) 56.8,74.23 56.8,81.57 58.86,83.63 66.28,83.63 67.84,85.19 67.84,85.62 C118.1
HDMI_TX0_D0P: length 23.8
  TOP w0.107: v1(56.33,74.04) 56.52,73.85 56.52,73.05 56.14,72.67 56.14,72.26 56.08,72.2 J6.35
  BOTTOM w0.107: v1(56.33,74.04) 56.52,74.23 56.52,81.69 58.74,83.91 66.16,83.91 67.55,85.31 67.55,85.62 C117.1
HDMI_TX0_D1N: length 25.7
  TOP w0.107: J6.33 55.68,71.01 55.63,70.96 55.63,70.66 v1(55.81,70.49)
  BOTTOM w0.107: C115.1 65.52,85.59 65.52,84.9 64.96,84.34 57.38,84.34 55.54,82.5 55.54,78.86 55.81,78.59 55.81,72.47 55.62,72.29 55.62,71.07 55.81,70.88 v1(55.81,70.49)
HDMI_TX0_D1P: length 25.7
  TOP w0.107: J6.31 55.28,71.01 55.35,70.94 55.35,70.69 v1(55.15,70.49)
  BOTTOM w0.107: v1(55.15,70.49) 55.15,70.88 55.34,71.07 55.34,72.41 55.52,72.59 55.52,78.47 55.25,78.74 55.25,82.62 57.26,84.62 64.84,84.62 65.24,85.02 65.24,85.65 C114.1
HDMI_TX0_D2N: length 23.4
  TOP w0.107: v1(55.01,74.04) 54.82,73.85 54.82,72.26 54.88,72.2 J6.29
  BOTTOM w0.107: C116.1 63.22,85.58 63.22,85.39 62.9,85.06 61.8,85.06 61.34,85.52 55.97,85.52 54.28,83.83 54.28,78.15 54.82,77.61 54.82,74.23 v1(55.01,74.04)
HDMI_TX0_D2P: length 23.3
  TOP w0.107: v1(54.35,74.04) 54.54,73.85 54.54,72.26 54.48,72.2 J6.27
  BOTTOM w0.107: v1(54.35,74.04) 54.54,74.23 54.54,77.49 53.99,78.04 53.99,83.95 55.85,85.8 61.46,85.8 61.91,85.35 62.78,85.35 62.94,85.51 62.94,85.66 C113.1
HDMI_TX0_D3N: length 27.3
  TOP w0.107: v1(57.41,70.49) 57.23,70.66 57.23,70.96 57.28,71.01 J6.41
  BOTTOM w0.107: v1(57.41,70.49) 57.41,70.88 57.22,71.07 57.22,73.17 57.9,73.84 57.9,81.35 59.43,82.88 66.78,82.88 68.84,84.93 69.91,84.93 70.25,85.27 70.25,85.62 C120.1
HDMI_TX0_D3P: length 27.3
  TOP w0.107: v1(56.75,70.49) 56.95,70.69 56.95,70.94 56.88,71.01 J6.39
  BOTTOM w0.107: v1(56.75,70.49) 56.75,70.88 56.94,71.07 56.94,73.28 57.61,73.96 57.61,81.46 59.32,83.17 66.67,83.17 68.72,85.22 69.79,85.22 69.96,85.39 69.96,85.62 C119.1
HDMI_TX0_HPD_M0: length 38.2
  TOP w0.152: v1(73.26,80.03) 73.87,80.64 76.07,80.64 77.34,81.91 77.34,92.71 76.83,93.22 v1(76.83,96.26) ; J6.92 67.28,75.79 67.69,76.2 v1(67.94,76.2)
  BOTTOM w0.152: v1(67.94,76.2) 68.6,76.85 69.43,76.85 72.62,80.03 v1(73.26,80.03) ; v1(76.83,96.26) 76.07,97.03 72.01,97.03 71.63,97.41 71.63,99.19 71.25,99.57 R133.2 70.1,99.07 Q10.3
HDMI_TX0_SBDN: length 24.2
  TOP w0.107: J6.47 58.48,72.2 58.41,72.27 58.41,72.52 v1(58.61,72.73) ; v1(72.14,85.7) 72.29,85.85 73.13,85.85 73.47,86.19 73.47,86.31 C122.1
  BOTTOM w0.107: v1(72.14,85.7) 71.96,85.52 71.96,85.29 71.8,85.12 arc(71.77,85.05) 71.8,84.98 arc(71.82,84.91) 71.8,84.84 71.63,84.68 arc(71.56,84.65) 71.49,84.68 arc(71.42,84.71) 71.35,84.68 71.19,84.52 arc(71.16,84.45) 71.19,84.38 arc(71.22,84.31) 71.19,84.24 71.03,84.08 arc(70.96,84.05) 70.89,84.08 arc(70.82,84.11) 70.75,84.08 70.46,83.79 69.4,83.79 67.24,81.63 65.4,81.63 59.16,75.39 59.16,73.86 59.1,73.81 59.1,73.8 58.61,73.31 v1(58.61,72.73)
HDMI_TX0_SBDP: length 24.2
  TOP w0.107: C121.1 73.19,86.46 73.19,86.31 73.01,86.14 72.35,86.14 72.14,86.35 v1(72.14,86.36) ; v1(57.95,72.73) 58.12,72.55 58.12,72.25 58.08,72.2 J6.45
  BOTTOM w0.107: v1(57.95,72.73) 58.33,73.1 58.33,73.43 58.82,73.92 58.82,73.93 58.87,73.98 58.87,75.51 65.28,81.92 67.12,81.92 69.28,84.08 70.35,84.08 71.68,85.41 71.68,85.89 71.75,85.96 71.75,85.98 v1(72.14,86.36)
HDMI_TX0_SCL_M0: length 59.9
  TOP w0.152: v1(24.64,83.69) 25.61,82.72 30.36,82.72 32.81,80.28 32.81,78.93 34.51,77.22 J4.56
  ART03 w0.14: v1(56.13,90.68) 54.99,89.53 45.52,89.53 42.57,86.59 37.59,86.59 36.75,85.75 36.75,84.94 36.47,84.66 33.63,84.66 33.05,85.24 27.33,85.24 26.85,84.76 25.7,84.76 v1(24.64,83.69)
  BOTTOM w0.152: Q7.2 63.25,89.88 R127.2 62.23,89.28 61.79,89.72 57.09,89.72 v1(56.13,90.68)
HDMI_TX0_SDA_M0: length 63.4
  TOP w0.152: v1(25.65,83.69) 26.16,83.18 30.55,83.18 33.31,80.43 33.31,79.09 34.91,77.48 J4.58
  ART03 w0.14: v1(25.65,83.69) 26.16,84.2 36.83,84.2 38,85.37 39.47,85.37 40.05,85.95 42.58,85.95 45.71,89.08 55.55,89.08 v1(56.13,89.66)
  BOTTOM w0.152: v1(56.13,89.66) 56.52,89.28 61.59,89.28 62.21,88.67 66.81,88.67 R129.2 C123.2 69.6,89.88 Q8.2
HP_PLUG_IN_DET: length 165.4
  TOP w0.152: v1(8.13,20.83) 10.16,20.83 11.13,19.86 12.88,19.86 13.16,19.58 13.97,19.58 14.71,20.32 31.5,20.32 31.88,19.94 53.85,19.94 58.08,24.17 J5.46
  ART03 w0.14: v1(48.77,91.18) 48.26,90.68 45.15,90.68 43.89,89.43 39.19,89.43 36.91,87.15 33.55,87.15 32.64,86.23 28.73,86.23 28.09,86.87 26.04,86.87 25.17,86 24.36,86 23.52,85.17 19.76,85.17 18.57,83.97 12.32,83.97 11.3,82.96 11.3,75.69 10.41,74.8 10.41,33.4 7.72,30.71 7.72,21.23 v1(8.13,20.83)
  BOTTOM w0.152: R206.1 C186.1 48.36,95.11 48.77,94.71 v1(48.77,91.18)
HUB_3V3: length 10.2
  BOTTOM w0.254: 92.45,72.91 C111.1 89.28,72.91 R123.1 R122.1
  BOTTOM w0.305: U19.20 88.53,71.26 89.27,72 R123.1 ; C112.1 92.85,70.37 92.05,69.57 U19.1
HUB_DM1: length 26
  BOTTOM w0.135: R116.2 89.78,81.29 89.78,80.99 89.04,80.25 89.04,77.78 83.48,72.22 83.48,65.13 84.03,64.58 88.12,64.58 88.44,64.9 88.44,65.44 88.53,65.53 U19.11
HUB_DM2: length 28.9
  BOTTOM w0.135: U19.9 89.53,65.53 89.44,65.44 89.44,64.67 88.33,63.57 83.13,63.57 82.68,64.02 82.68,73.32 87.73,78.37 87.73,81.32 R112.2
HUB_DM3: length 6.1
  BOTTOM w0.135: R114.2 93.23,63.63 92.7,63.63 92.52,63.81 91.98,63.81 91.8,63.63 90.81,63.63 90.43,64.01 90.43,65.43 90.53,65.53 U19.7
HUB_DM4: length 14.3
  TOP w0.135: v1(98.02,67.08) 98.17,66.93 98.17,66.54 98.55,66.17 99.25,66.17 99.57,66.48 99.57,67.49 99.78,67.71 100.07,67.71 R182.2
  BOTTOM w0.135: U19.5 92.08,67.57 92.17,67.48 92.49,67.48 92.81,67.16 92.81,65.78 93.3,65.29 95.85,65.29 95.95,65.39 U18.5 U18.6 97.91,65.39 98.2,65.68 98.2,66.9 v1(98.02,67.08)
HUB_DP1: length 25.3
  BOTTOM w0.135: U19.12 88.03,65.53 88.12,65.44 88.12,65.03 87.99,64.9 84.16,64.9 83.79,65.26 83.79,72.09 88.57,76.87 arc(88.68,76.92) 88.79,76.87 arc(88.89,76.83) 89,76.87 89.17,77.04 arc(89.21,77.15) 89.17,77.25 arc(89.12,77.36) 89.17,77.47 89.35,77.65 89.35,80.12 90.09,80.86 90.09,81.34 R117.2
HUB_DP2: length 28.8
  BOTTOM w0.135: U19.10 89.03,65.53 89.12,65.44 89.12,64.8 88.2,63.88 83.26,63.88 82.99,64.15 82.99,73.19 85.75,75.96 arc(85.85,76) 85.95,75.96 arc(86.05,75.92) 86.15,75.96 86.33,76.14 arc(86.37,76.24) 86.33,76.34 arc(86.29,76.44) 86.33,76.54 86.51,76.72 arc(86.61,76.76) 86.71,76.72 arc(86.81,76.68) 86.91,76.72 87.09,76.9 arc(87.13,77) 87.09,77.1 arc(87.05,77.2) 87.09,77.3 87.28,77.48 arc(87.38,77.52) 87.47,77.48 arc(87.57,77.44) 87.67,77.48 87.86,77.66 arc(87.9,77.76) 87.86,77.86 arc(87.81,77.96) 87.86,78.06 88.04,78.24 88.04,81.32 R113.2
HUB_DP3: length 6.3
  BOTTOM w0.135: U19.8 90.03,65.49 90.12,65.4 90.12,63.88 90.68,63.32 93.53,63.32 R115.2
HUB_DP4: length 14.8
  TOP w0.135: v1(98.68,67.08) 98.49,66.89 98.49,66.67 98.68,66.48 99.12,66.48 99.26,66.61 99.26,67.62 R183.2
  BOTTOM w0.135: U19.6 92.08,67.08 92.17,67.17 92.36,67.17 92.5,67.03 92.5,65.66 93.17,64.98 95.88,64.98 95.97,64.89 U18.4 U18.7 97.85,64.89 98.51,65.55 98.51,65.86 arc(98.54,65.94) 98.62,65.97 arc(98.7,66) 98.73,66.08 98.73,66.4 arc(98.7,66.48) 98.62,66.51 arc(98.54,66.54) 98.51,66.62 98.51,66.9 98.68,67.07 v1(98.68,67.08)
I2C0_SCL_M2: length 143.1
  TOP w0.152: v1(33.53,13.71) 34.73,14.91 65.56,14.91 66.29,15.64 66.29,21.94 65.68,22.55 J5.84
  ART03 w0.14: v1(5.61,85.67) 3.99,84.04 3.99,71.42 3.63,71.07 3.63,69.09 3.28,68.73 3.28,59.97 3.63,59.61 3.63,43.23 6.12,40.74 6.12,18.9 7.05,17.97 7.95,17.97 10.3,15.62 17.91,15.62 18.29,15.24 32,15.24 v1(33.53,13.71)
  BOTTOM w0.152: v1(5.61,85.67) 5.87,85.41 U8.6
I2C0_SDA_M2: length 144.5
  TOP w0.152: v1(34.42,13.71) 35.18,14.48 65.82,14.48 66.71,15.37 66.71,22.09 66.08,22.72 J5.86
  ART03 w0.14: v1(34.42,13.71) 33.78,14.35 33.54,14.35 32.02,15.87 23.88,15.87 23.47,16.28 10.5,16.28 8.14,18.64 7.14,18.64 6.6,19.18 6.6,41.02 3.99,43.64 3.99,70.92 4.45,71.37 4.45,83.77 6.1,85.42 6.1,86.26 v1(5.61,86.74)
  BOTTOM w0.152: U8.5 5.93,86.06 5.61,86.38 v1(5.61,86.74)
I2C1_SCL_M2: length 204.7
  TOP w0.152: v1(81.53,14.86) 81.28,15.11 69.59,15.11 67.11,17.59 67.11,22.3 66.48,22.93 J5.88
  BOTTOM w0.152: J23.6 125.68,24.75 123.83,22.89 R163.2 124.37,19.13 124.37,17.14 122.6,15.37 82.04,15.37 v1(81.53,14.86) 79.38,14.86 78.87,14.35 78.87,9.52 78.33,8.99 34.14,8.99 32.51,10.62 32.51,17.45 31.53,18.43 31.53,20.92 29.52,22.93 29.52,28.25 31.11,29.84 31.11,31.75 29.9,32.97 29.9,34.64 28.32,36.22 18.58,36.22 17.77,37.03 17.77,57.35 22.5,62.07 22.5,65.54 R230.2 22.99,66.28 U39.6
I2C1_SDA_M2: length 207
  TOP w0.152: v1(82.55,14.86) 81.79,15.62 69.78,15.62 67.48,17.92 67.48,22.52 66.88,23.12 J5.90
  BOTTOM w0.152: J23.5 125.72,24.25 124.26,22.79 124.26,20.38 R161.2 125.6,19.04 125.6,17.65 122.81,14.86 v1(82.55,14.86) 82.02,14.33 79.74,14.33 79.5,14.1 79.5,9.4 78.54,8.43 33.99,8.43 32,10.41 32,17.07 30.96,18.11 30.96,20.6 28.96,22.6 28.96,28.57 30.48,30.1 30.48,31.62 29.39,32.71 29.39,34.39 27.99,35.79 18.4,35.79 17.34,36.85 17.34,57.57 21.72,61.95 21.72,63.19 21.03,63.88 21.03,65.22 R231.2 22.49,66.68 U39.7
I2C2_SCL_M4: length 150.1
  TOP w0.152: v1(128.91,46.86) 130.66,46.86 131.22,47.42 131.22,57.81 131.6,58.19 131.6,63.93 131.14,64.39 v1(131.14,64.62) ; v1(58.31,19.56) 58.31,21.48 59.68,22.85 J5.54
  ART03 w0.14: v1(58.31,19.56) 58.8,19.06 58.8,17.78 59.31,17.27 75.06,17.27 75.44,17.65 76.83,17.65 77.62,16.86 104.75,16.86 107.06,19.18 120.78,19.18 v1(121.92,18.03)
  BOTTOM w0.132: 129.69,76.71 129.1,77.3 128.71,77.3 128.14,76.73 127.7,76.73 127.19,77.24 J19.9 ; v1(131.14,64.62) 131.62,65.1
  BOTTOM w0.152: J19.9 124.8,77.24 R148.2 ; v1(128.91,46.86) 128.79,46.75 J21.6 126.45,46.76 123.96,46.76 121.74,44.54 121.74,29.26 122.79,28.21 122.79,18.9 v1(121.92,18.03) ; 129.69,76.71 130.68,76.71 131.62,75.77 131.62,65.1
I2C2_SDA_M4: length 149.3
  TOP w0.152: v1(127.89,45.85) 128.4,46.35 131.6,46.35 131.93,46.69 131.93,64.38 131.72,64.6 131.72,65.04 v1(131.14,65.62) ; v1(59.31,19.56) 59.31,21.72 60.08,22.49 J5.56
  ART03 w0.14: v1(59.31,19.56) 59.31,18.03 59.56,17.78 74.8,17.78 75.18,18.16 77.22,18.16 78.05,17.32 104.44,17.32 106.81,19.68 121.16,19.68 v1(122.81,18.03)
  BOTTOM w0.132: J19.10 127.17,76.74 127.58,76.33 127.99,76.33 128.62,75.69 129.13,75.69 129.53,76.1
  BOTTOM w0.152: J19.10 124.68,76.74 123.95,77.47 R152.2 ; 129.53,76.1 130.44,76.1 131.14,75.4 v1(131.14,65.62) ; v1(122.81,18.03) 123.2,18.42 123.2,28.42 122.17,29.45 122.17,44.45 124.08,46.35 125.35,46.35 125.45,46.25 J21.5 127.49,46.25 v1(127.89,45.85)
I2C5_SCL_M3: length 124.6
  TOP w0.152: J20.9 125.23,70.74 v1(124.33,69.85) ; v1(75.56,16.13) 69.82,16.13 67.96,18 67.96,22.8 67.28,23.48 J5.92 ; J22.6 125.1,53.25 124.97,53.38 124.97,55.27 123.22,57.02 v1(123.06,57.02)
  BOTTOM w0.152: v1(124.33,69.85) 124.21,69.98 R150.2 122.48,68.89 122.48,57.61 v1(123.06,57.02) 122.28,57.02 117.6,52.35 117.6,43.29 118.89,42 118.89,31.13 116.33,28.58 116.33,16.9 116.04,16.61 76.05,16.61 v1(75.56,16.13)
I2C5_SDA_M3: length 124.9
  TOP w0.152: v1(124.33,70.99) 124.59,71.25 J20.10 ; v1(76.58,16.13) 76.07,16.64 69.97,16.64 68.39,18.22 68.39,23 67.68,23.71 J5.94 ; J22.5 125.61,53.75 125.48,53.88 125.48,55.62 v1(124.08,57.02)
  BOTTOM w0.152: v1(76.58,16.13) 116.33,16.13 116.77,16.56 116.77,28.4 119.32,30.95 119.32,42.19 118.06,43.45 118.06,52.15 122.06,56.16 123.22,56.16 v1(124.08,57.02) 123.57,57.53 123.57,67.87 124.97,69.26 124.97,70.36 v1(124.33,70.99) R154.2
I2C7_SCL_M0_CODEC: length 58.2
  TOP w0.152: v1(57.15,37.72) 64.01,37.72 64.48,37.25 J5.77
  BOTTOM w0.152: v1(57.15,37.72) 57.53,37.72 58.8,38.99 58.8,41.22 56.37,43.65 56.37,66.12 56.07,66.42 54.87,66.42 R185.2 53.59,67.7 53.59,69.47 51.18,71.88 51.18,73.47 50.88,73.78 R197.1
I2C7_SDA_M0_CODEC: length 61.4
  TOP w0.152: J5.75 64.08,36.83 63.7,37.21 57.91,37.21 v1(57.15,36.45)
  BOTTOM w0.152: v1(57.15,36.45) 59.24,38.54 59.24,41.47 56.81,43.9 56.81,67.38 56.52,67.67 54.77,67.67 R188.2 54.24,69.46 51.56,72.13 51.56,74 51.26,74.31 49.93,74.31 R198.1
I2C8_SCL_M2: length 86
  TOP w0.152: v1(75.56,17.14) 70.15,17.14 68.74,18.55 68.74,23.28 68.08,23.94 J5.96 ; J24.6 127.9,31.25 128.52,31.88 130.93,31.88 131.19,31.62 131.19,23.35 130.57,22.73 128.14,22.73 127.25,21.84 126.47,21.84 125.07,20.45 124.62,20.45 123.85,19.68 R164.2 122.04,19.68 120.56,18.2 v1(115.82,18.2)
  BOTTOM w0.152: v1(75.56,17.14) 76.07,17.65 115.28,17.65 v1(115.82,18.2)
I2C8_SDA_M2: length 89.1
  TOP w0.152: v1(76.58,17.14) 76.07,17.65 70.24,17.65 69.16,18.72 69.16,23.38 68.48,24.06 J5.98 ; v1(115.82,17.09) 125.17,17.09 125.73,17.65 125.73,18.91 R162.2 126.7,21.41 127.43,21.41 128.25,22.22 130.68,22.22 131.7,23.24 131.7,31.73 131.11,32.31 128.25,32.31 127.69,31.75 J24.5
  BOTTOM w0.152: v1(76.58,17.14) 115.77,17.14 v1(115.82,17.09)
I2C_ADDR_SET: length 2.8
  BOTTOM w0.152: U33.26 49.22,71.05 49.02,71.25 49.02,72.14 R200.2
I2S0_LRCK: length 47.7
  TOP w0.152: v1(56.13,38.99) 56.69,39.55 65.45,39.55 66.08,38.92 J5.85
  BOTTOM w0.152: R194.1 51.18,61.21 54.43,57.96 54.43,42.7 56.62,40.51 56.62,39.47 v1(56.13,38.99)
I2S0_MCLK: length 49.8
  TOP w0.152: J5.81 65.28,29.94 65,30.22 65,37.64 64.29,38.35 56.77,38.35 v1(56.13,37.72)
  BOTTOM w0.152: v1(56.13,37.72) 56.77,38.35 57.4,38.35 58.29,39.24 58.29,41.02 55.88,43.43 55.88,65.14 R190.1
I2S0_SCLK: length 45.2
  TOP w0.152: J5.83 65.68,30.18 65.46,30.4 65.46,38.68 65.15,38.99 v1(57.15,38.99)
  BOTTOM w0.152: R191.1 53.21,60.83 55.37,58.67 55.37,43.18 57.75,40.8 57.75,39.59 v1(57.15,38.99)
I2S0_SDI0: length 49.9
  TOP w0.152: J5.89 66.88,30 67.21,30.33 67.21,34.47 67.74,35 67.74,40.28 67.13,40.89 56.77,40.89 v1(56.13,40.26)
  BOTTOM w0.152: v1(56.13,40.26) 53.9,42.49 53.9,57.76 50.16,61.49 R195.1
I2S0_SDO0: length 46.2
  TOP w0.152: J5.87 66.48,30.31 66.75,30.58 66.75,39.57 66.07,40.26 v1(57.15,40.26)
  BOTTOM w0.152: v1(57.15,40.26) 57.15,40.63 54.89,42.89 54.89,58.32 52.2,61.01 R193.1
LCD0_BL_PWM: length 79.9
  TOP w0.152: J6.85 66.08,72.51 v1(66.02,72.57) ; v1(91.57,79.36) 91.08,79.84 87.77,79.84 85.88,77.95 82.19,77.95 80.64,79.5 76.79,79.5 v1(76.26,80.03) ; v1(124.9,82.7) 124.87,82.67 124.87,75.67 v1(125.35,75.18)
  ART03 w0.14: v1(124.9,82.7) 124.9,81.47 124.46,81.02 123.67,81.02 122.13,79.49 118.59,79.49 117.67,78.57 97.11,78.57 96.05,79.63 91.84,79.63 v1(91.57,79.36)
  BOTTOM w0.152: J19.13 125.41,75.24 v1(125.35,75.18) ; v1(66.02,72.57) 66.02,71.6 66.53,71.09 69.67,71.09 69.98,71.4 69.98,73.2 75.67,78.89 75.67,79.44 v1(76.26,80.03)
LCD0_PWR_EN: length 133.9
  TOP w0.152: J5.59 60.88,30.72 v1(60.1,31.49) ; v1(130.68,58.16) 131.14,58.62 131.14,63.55 130.66,64.03 130.66,81.74 130.94,82.02 R156.1
  ART03 w0.14: v1(60.1,31.49) 60.59,31.98 60.59,31.98 62.78,34.16 102.69,34.16 103,34.47 103,44.58 103.5,45.08 114.88,45.08 118.95,41.02 128.02,41.02 130.3,43.31 130.3,55.62 129.33,56.6 129.33,57.96 129.54,58.16 v1(130.68,58.16)
LCD0_RST: length 134.6
  TOP w0.152: J5.66 62.08,23.14 62.48,22.73 62.48,18.91 61.99,18.41 v1(61.47,18.41)
  ART03 w0.14: v1(61.47,18.41) 74.68,18.41 74.93,18.67 77.6,18.67 78.46,17.8 104.04,17.8 106.43,20.19 127.25,20.19 129.22,22.16 129.22,28.41 130.81,30 130.81,37.07 131.24,37.51 131.24,56.34 v1(130.68,56.89)
  BOTTOM w0.152: J19.15 128.19,74.24 128.57,73.86 129.09,73.86 129.78,73.17 130.07,73.17 130.63,72.61 130.63,62.84 131.19,62.28 131.19,57.4 v1(130.68,56.89)
LCD1_BL_PWM: length 80.7
  TOP w0.152: v1(66.02,73.57) 66.51,73.08 66.51,72.37 66.48,72.34 J6.87 ; J20.13 125.38,72.74 124.37,73.76 124.37,74.77 123.83,75.31 123.83,80.5 v1(123.84,80.52) ; v1(76.26,79.03) 80.54,79.03 82.06,77.52 86.06,77.52 87.9,79.36 v1(90.57,79.36)
  ART03 w0.14: v1(90.57,79.36) 91.08,78.84 91.9,78.84 92.23,79.17 95.81,79.17 96.74,78.24 117.83,78.24 118.64,79.05 122.37,79.05 v1(123.84,80.52)
  BOTTOM w0.152: v1(76.26,79.03) 76.24,79.03 70.41,73.2 70.41,70.97 70.1,70.66 66.04,70.66 65.53,71.17 65.53,73.07 v1(66.02,73.57)
LCD1_PWR_EN: length 94.4
  TOP w0.152: v1(120.78,40.38) 119.25,40.38 118.74,40.9 R155.1 ; v1(61.1,31.49) 61.28,31.32 J5.61
  ART03 w0.14: v1(120.78,40.38) 119.13,40.38 114.86,44.65 103.94,44.65 103.63,44.35 103.63,34.16 103.1,33.63 63.24,33.63 v1(61.1,31.49)
LCD1_RST: length 80.8
  TOP w0.152: v1(123.83,81.53) 124.37,80.99 124.37,75.5 124.84,75.02 124.84,73.96 125.14,73.66 126.42,73.66 J20.15 ; v1(62.65,80.39) 62.65,79.63 60.88,77.86 J6.60
  ART03 w0.14: v1(62.65,80.39) 63.2,80.93 63.2,81.63 63.47,81.91 68.88,81.91 69.77,81.02 76.99,81.02 77.55,80.47 88.82,80.47 89.87,81.51 96.57,81.51 97,81.08 105.63,81.08 106.8,79.91 116.94,79.91 117.22,80.19 117.22,80.71 117.5,80.99 122.71,80.99 123.25,81.53 v1(123.83,81.53)
MDIN0_PHY: length 30.9
  TOP w0.107: v1(109.99,82.17) 109.99,82.12 109.77,81.89 109.77,81.66 arc(109.78,81.61) 109.83,81.6 arc(109.9,81.57) 109.93,81.5 109.93,81.27 arc(109.9,81.2) 109.83,81.17 arc(109.78,81.15) 109.77,81.11 109.77,80.87 110,80.64 110.32,80.64 arc(110.39,80.67) 110.41,80.74 arc(110.45,80.82) 110.54,80.86 110.72,80.86 arc(110.8,80.82) 110.84,80.74 arc(110.87,80.67) 110.93,80.64 115.76,80.64 117.27,82.16 117.95,82.16 118.76,82.96 118.99,82.96 arc(119.05,82.98) 119.07,83.04 arc(119.1,83.1) 119.15,83.12 119.42,83.12 arc(119.48,83.1) 119.5,83.04 arc(119.52,82.98) 119.58,82.96 120.09,82.96 121.32,84.19 121.32,86.27 121.07,86.52 120.97,86.57 120.84,86.52 J15.3
  BOTTOM w0.107: v1(109.99,82.17) 109.81,81.98 109.81,72.44 110.17,72.08 110.17,71.31 110.23,71.25 U14.2
MDIN1_PHY: length 31.3
  TOP w0.107: v1(111.62,82.17) 111.44,81.98 111.44,81.47 111.57,81.34 115.47,81.34 116.98,82.85 117.67,82.85 118.71,83.9 118.71,85.86 117.44,87.13 117.44,88.57 117.25,88.76 115.95,88.76 115.1,87.9 J15.7
  BOTTOM w0.107: v1(111.62,82.17) 111.37,81.91 111.37,71.34 111.43,71.28 U14.5
MDIN2_PHY: length 23.1
  TOP w0.107: J15.6 116.94,86.6 116.89,86.45 116.78,86.39 116.33,85.94 116.33,83.18 115.18,82.04 114.61,82.04 arc(114.56,82.05) 114.54,82.1 arc(114.51,82.17) 114.44,82.2 114.22,82.2 arc(114.15,82.17) 114.12,82.1 arc(114.1,82.05) 114.06,82.04 113.75,82.04 arc(113.71,82.05) 113.69,82.1 arc(113.66,82.17) 113.58,82.2 113.37,82.2 arc(113.29,82.17) 113.26,82.1 arc(113.25,82.05) 113.2,82.04 112.97,82.04 112.82,82.18 112.82,82.85 v1(113.03,83.06)
  BOTTOM w0.107: U14.7 112.23,71.41 112.18,71.46 112.18,72.22 112.06,72.33 112.06,75.74 112.78,76.46 112.78,82.81 v1(113.03,83.06)
MDIN3_PHY: length 19.6
  TOP w0.107: v1(114.92,82.5) 114.75,82.67 114.09,82.67 113.76,83 113.76,85.74 113.33,86.17 113.33,86.17 113.13,86.17 112.94,85.98 J15.9
  BOTTOM w0.107: U14.10 113.43,71.41 113.39,71.46 113.39,71.95 113.67,72.23 113.67,80.23 arc(113.7,80.31) 113.78,80.35 arc(113.86,80.38) 113.89,80.46 113.89,80.66 arc(113.86,80.74) 113.78,80.77 arc(113.7,80.81) 113.67,80.89 113.67,81.09 arc(113.7,81.17) 113.78,81.2 arc(113.86,81.23) 113.89,81.31 113.89,81.51 arc(113.86,81.59) 113.78,81.63 arc(113.7,81.66) 113.67,81.74 113.67,82.11 114.23,82.68 114.72,82.68 114.9,82.5 v1(114.92,82.5)
